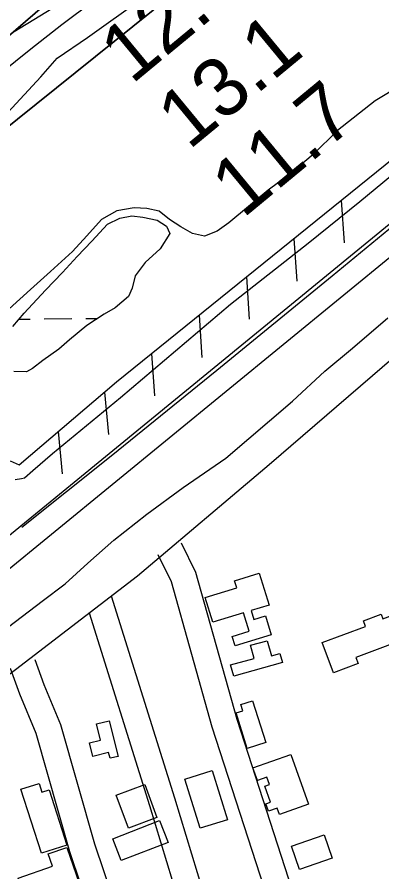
# Model space of a CAD drawing. Extents: x 3598634 to 3636690, y 517270 to 542944.
# Drawn here: x 3609937 to 3610356, y 530075 to 531057 of the extents above; entities that cross this region are included whole.
import ezdxf

# ---------------------------------------------------------------- set-up
doc = ezdxf.new("R2010")
doc.units = 0
for name, color, linetype in [('V-BLDG-OTLN', 7, 'Continuous'), ('V-FLOD-BASE', 7, 'Continuous'), ('V-LEVE-TOET', 7, 'Continuous'), ('V-RIVR-EDGE', 7, 'Continuous'), ('V-RIVR-RANG', 7, 'Continuous'), ('V-ROAD-CNTR', 7, 'Continuous'), ('V-RRAP-FSHR', 7, 'Continuous'), ('V-SITE-VEGE', 7, 'Continuous'), ('V-SURV-LINE', 7, 'Continuous'), ('V-TOPO-DPTH', 7, 'Continuous'), ('V-TOPO-MINR', 7, 'Continuous'), ('V-TOPO-WATR', 7, 'Continuous'), ('V-WETL-SWMP', 7, 'Continuous')]:
    doc.layers.add(name, color=color, linetype=linetype)

msp = doc.modelspace()

# ---------------------------------------------------------------- linework, layer by layer
at = {"layer": 'V-BLDG-OTLN'}
for points in [[(3610228.6, 530347.04), (3610187.05, 530334.22), (3610183.75, 530344.93), (3610203.25, 530350.94), (3610196.65, 530372.34), (3610161.52, 530361.51), (3610152.85, 530389.65), (3610188.94, 530400.78), (3610186.38, 530409.07), (3610214.78, 530417.83), (3610226.1, 530381.11), (3610205.42, 530374.73), (3610208.52, 530364.67), (3610221.9, 530368.79)], [(3610398.09, 530347.91), (3610325.87, 530320.89), (3610328.52, 530313.8), (3610300.09, 530303.17), (3610287.09, 530337.92), (3610336.91, 530356.56), (3610334.52, 530362.95), (3610355.1, 530370.65), (3610357.05, 530365.47), (3610387.29, 530376.78)], [(3610241.45, 530315.01), (3610185.59, 530299.51), (3610182.01, 530312.42), (3610208.89, 530319.88), (3610204.74, 530334.85), (3610223.95, 530340.17), (3610228.77, 530322.79), (3610238.54, 530325.5)], [(3610201.01, 530216.43), (3610188.19, 530257.31), (3610196.01, 530259.76), (3610193.79, 530266.86), (3610207.22, 530271.07), (3610222.27, 530223.09)], [(3610042.51, 530248.19), (3610052.6, 530207.32), (3610043.47, 530205.07), (3610041.8, 530211.8), (3610023.72, 530207.33), (3610019.87, 530222.96), (3610032.49, 530226.08), (3610027.93, 530244.59)], [(3610251.35, 530209.48), (3610271.61, 530152.25), (3610237.95, 530140.33), (3610235.32, 530147.76), (3610225.31, 530144.21), (3610222.3, 530152.7), (3610227.95, 530154.7), (3610221.42, 530173.16), (3610226.47, 530174.94), (3610223.45, 530183.47), (3610212.67, 530179.66), (3610207.59, 530193.99)], [(3610146.98, 530124.7), (3610129.44, 530181.24), (3610160.7, 530190.94), (3610178.23, 530134.39)], [(3609964.48, 530095.95), (3609940.87, 530169.52), (3609961.78, 530176.23), (3609965.01, 530166.16), (3609973.51, 530168.89), (3609993.89, 530105.38)], [(3610097.32, 530137.09), (3610064.62, 530124.93), (3610050.6, 530162.64), (3610083.31, 530174.79)], [(3610110.18, 530108.46), (3610056.35, 530087.52), (3610046.58, 530112.6), (3610100.41, 530133.55)], [(3610298.66, 530090.23), (3610261.19, 530077.41), (3610252, 530104.25), (3610289.48, 530117.07)], [(3609993.77, 530102.67), (3610007.95, 530061.79), (3609947.14, 530040.7), (3609937.87, 530067.44), (3609977.12, 530081.05), (3609972.22, 530095.2)]]:
    msp.add_lwpolyline(points, close=True, dxfattribs=at)
at = {"layer": 'V-FLOD-BASE'}
msp.add_lwpolyline([(3609942.05, 530470.58), (3610044.66, 530552.47), (3610166.13, 530651.03), (3610298.76, 530759.3), (3610396.5, 530839.81), (3610523.55, 530943.92)], dxfattribs=at)
at = {"layer": 'V-LEVE-TOET'}
for points in [[(3610385.49, 530889.98), (3610330.34, 530844.18), (3610271.01, 530796.29), (3610181.66, 530726.2), (3610055.3, 530619.3), (3609977.11, 530554.75), (3609954.77, 530535.32), (3609944.99, 530526.99), (3609941.51, 530526.3), (3609934.54, 530524.93)], [(3609579.4, 530055.82), (3609660.42, 530134.99), (3609723.93, 530182.87), (3609766.51, 530216.87), (3609796.54, 530244.65), (3609827.97, 530276.59), (3609860.09, 530305.75), (3609918.72, 530350.16), (3609965.48, 530385.55), (3609992.01, 530405.67), (3610017.85, 530429.28), (3610047.87, 530455.66), (3610085.56, 530485.5), (3610127.44, 530516.02), (3610176.28, 530550.01), (3610253.08, 530615.26), (3610290.09, 530649.98), (3610322.2, 530676.35), (3610362.7, 530711.06)]]:
    msp.add_lwpolyline(points, dxfattribs=at)
at = {"layer": 'V-RIVR-EDGE'}
msp.add_lwpolyline([(3609933.36, 531039.95), (3609992.29, 531075.83)], dxfattribs=at)
at = {"layer": 'V-ROAD-CNTR'}
for points in [[(3609139.7, 529575.2), (3609208.82, 529647.87), (3609297.62, 529739.46), (3609401.37, 529840.42), (3609559.65, 529992.91), (3609748.65, 530152.62), (3609891.27, 530274.15), (3610074.88, 530414.76), (3610226.26, 530542.4), (3610422.26, 530711.54)], [(3610125.23, 530452.45), (3610141.62, 530418.95), (3610189.2, 530249.99), (3610299.07, 529910.47), (3610355.94, 529737.7), (3610382.32, 529651.8)], [(3610098.28, 530439.26), (3610113.48, 530408.2), (3610160.48, 530241.3), (3610270.55, 529901.16), (3610327.35, 529728.6), (3610353.65, 529642.99)], [(3610044.85, 530391.76), (3610117.56, 530159.58), (3610182.62, 529945.34), (3610281.68, 529623.45), (3610358.44, 529384.96), (3610436.87, 529108.73), (3610504.84, 528885.32), (3610568.81, 528678.82)], [(3610019.49, 530372.34), (3610088.89, 530150.74), (3610153.93, 529936.57), (3610253.06, 529614.44), (3610329.72, 529376.26), (3610408.08, 529100.26), (3610476.16, 528876.52), (3610540.16, 528669.94)], [(3609957.03, 530318.75), (3609967.34, 530289.94), (3609986.39, 530243.73), (3610025.65, 530106.88), (3610077.44, 529952.45), (3610121.03, 529809.11), (3610177.74, 529626.09), (3610246.01, 529383.99), (3610305.06, 529198.16), (3610409.54, 528846.2), (3610491.37, 528582.36), (3610603.11, 528221.45), (3610681.79, 527958.73), (3610748.76, 527716.35)], [(3609928.78, 530308.64), (3609939.33, 530279.16), (3609958.02, 530233.84), (3609996.99, 530097.97), (3610048.86, 529943.31), (3610092.35, 529800.31), (3610148.97, 529617.58), (3610217.27, 529375.37), (3610276.38, 529189.35), (3610380.83, 528837.49), (3610462.72, 528573.48), (3610574.41, 528212.71), (3610652.96, 527950.43), (3610719.85, 527708.36)]]:
    msp.add_lwpolyline(points, dxfattribs=at)
at = {"layer": 'V-RRAP-FSHR'}
for p, q in [((3610309.06, 530846.07), (3610312.4, 530797.36)), ((3610254.6, 530802.1), (3610257.93, 530753.38)), ((3610200.13, 530758.12), (3610203.47, 530709.41)), ((3610145.67, 530714.15), (3610149.01, 530665.43)), ((3610091.21, 530670.17), (3610094.55, 530621.46)), ((3610037.05, 530625.83), (3610041.68, 530577.22)), ((3609983.78, 530580.42), (3609988.41, 530531.81))]:
    msp.add_line(p, q, dxfattribs=at)
msp.add_lwpolyline([(3609928.71, 530546.83), (3609939.14, 530542.37), (3610050.89, 530637.62), (3610449.17, 530959.2)], dxfattribs=at)
at = {"layer": 'V-SITE-VEGE'}
for points in [[(3609925.99, 530947.01), (3609963.72, 530987.99), (3609982.58, 531009.53), (3610017.47, 531033.11), (3610080.28, 531078.2)], [(3610378.08, 530978.46), (3610348.08, 530960.43), (3610304.81, 530926.43), (3610276.87, 530898.65), (3610250.34, 530876.44), (3610225.21, 530857.71), (3610179.84, 530820.23), (3610166.58, 530810.51), (3610151.94, 530804.98), (3610138.02, 530807.81), (3610124.8, 530815.51), (3610111.6, 530823.9), (3610099.78, 530833.69), (3610085.86, 530836.52), (3610071.24, 530837.25), (3610051.03, 530833.83), (3610033.59, 530824.12), (3610016.83, 530805.37), (3610000.06, 530787.31), (3609974.92, 530764.4), (3609951.88, 530743.57), (3609927.44, 530721.35)]]:
    msp.add_lwpolyline(points, dxfattribs=at)
at = {"layer": 'V-SURV-LINE'}
for points in [[(3609502.41, 530113.39), (3610747.34, 531132.5)], [(3610766.34, 531109.28), (3609521.41, 530090.17)]]:
    msp.add_lwpolyline(points, dxfattribs=at)
at = {"layer": 'V-TOPO-DPTH'}
for points in [[(3610396.04, 531284.42), (3610317.47, 531229.87), (3610285.5, 531207.48), (3610253.66, 531184.93), (3610221.99, 531162.13), (3610190.44, 531139.16), (3610141.23, 531103.02), (3610134.42, 531097.95), (3610127.65, 531092.81), (3610120.94, 531087.59), (3610114.29, 531082.31), (3609870.36, 530886.11), (3609795.14, 530824.57), (3609720.6, 530762.22), (3609647.1, 530698.65), (3609574.3, 530634.26), (3609459.27, 530530.84), (3609444.63, 530517.43), (3609430.15, 530503.83), (3609415.93, 530489.97), (3609401.88, 530475.93), (3608847.69, 529911.87)], [(3610068.36, 531157.33), (3609537.58, 530699.57), (3609510.2, 530675.73), (3609482.96, 530651.71), (3609455.95, 530627.44), (3609429.1, 530603), (3609385.29, 530562.76), (3609380.49, 530558.27), (3609375.74, 530553.74), (3609371.07, 530549.12), (3609366.45, 530544.45), (3609245.63, 530420.27), (3609181.06, 530353.08), (3609117.05, 530285.37)], [(3609117.05, 530285.37), (3609181.06, 530353.08), (3609245.63, 530420.27), (3609366.45, 530544.45), (3609371.07, 530549.12), (3609375.74, 530553.74), (3609380.49, 530558.27), (3609385.29, 530562.76), (3609429.1, 530603), (3609455.95, 530627.44), (3609482.96, 530651.71), (3609510.2, 530675.73), (3609537.58, 530699.57), (3610068.36, 531157.33)]]:
    msp.add_lwpolyline(points, dxfattribs=at)
at = {"layer": 'V-TOPO-MINR'}
for points in [[(3608847.69, 529911.87), (3609401.88, 530475.93), (3609415.93, 530489.97), (3609430.15, 530503.83), (3609444.63, 530517.43), (3609459.27, 530530.84), (3609574.3, 530634.26), (3609647.1, 530698.65), (3609720.6, 530762.22), (3609795.14, 530824.57), (3609870.36, 530886.11), (3610114.29, 531082.31), (3610120.94, 531087.59), (3610127.65, 531092.81), (3610134.42, 531097.95), (3610141.23, 531103.02), (3610190.44, 531139.16), (3610221.99, 531162.13), (3610253.66, 531184.93), (3610285.5, 531207.48), (3610317.47, 531229.87), (3610396.04, 531284.42)], [(3609916.83, 530991.68), (3609952.24, 531020.08), (3609988.09, 531047.92), (3610024.25, 531075.39)]]:
    msp.add_lwpolyline(points, dxfattribs=at)
at = {"layer": 'V-TOPO-WATR'}
msp.add_lwpolyline([(3609117.05, 530285.37), (3609181.06, 530353.08), (3609245.63, 530420.27), (3609366.45, 530544.45), (3609371.07, 530549.12), (3609375.74, 530553.74), (3609380.49, 530558.27), (3609385.29, 530562.76), (3609429.1, 530603), (3609455.95, 530627.44), (3609482.96, 530651.71), (3609510.2, 530675.73), (3609537.58, 530699.57), (3610068.36, 531157.33)], dxfattribs=at)
at = {"layer": 'V-WETL-SWMP'}
for p, q in [((3609967.62, 530709.88), (3609999.62, 530710.18)), ((3610015.62, 530710.33), (3610029.06, 530710.45)), ((3609938.92, 530709.61), (3609951.62, 530709.73))]:
    msp.add_line(p, q, dxfattribs=at)
msp.add_lwpolyline([(3609931.56, 530701.14), (3609944.83, 530716.43), (3609969.29, 530742.82), (3609988.84, 530762.96), (3610005.61, 530781.72), (3610022.38, 530799.08), (3610040.54, 530818.53), (3610054.49, 530825.46), (3610068.43, 530828.2), (3610080.96, 530826.78), (3610097.66, 530823.25), (3610108.09, 530816.25), (3610112.25, 530807.88), (3610101.05, 530790.5), (3610083.6, 530774.53), (3610072.41, 530759.24), (3610068.89, 530745.32), (3610064.68, 530735.59), (3610049.32, 530722.4), (3610036.77, 530715.47), (3610016.53, 530702.29), (3609996.98, 530685.63), (3609984.42, 530675.22), (3609966.27, 530662.04), (3609954.41, 530653.02), (3609947.43, 530648.86), (3609932.81, 530649.6)], dxfattribs=at)

# ---------------------------------------------------------------- texts
at = {"layer": 'V-RIVR-RANG'}
for s, p in [('12.5', (3610068.21, 530978.46)), ('13.1', (3610133.92, 530903.03)), ('11.7', (3610195.96, 530824.57))]:
    msp.add_text(s, height=67, rotation=39.55833, dxfattribs=at).set_placement(p)

doc.saveas('drawing.dxf')
